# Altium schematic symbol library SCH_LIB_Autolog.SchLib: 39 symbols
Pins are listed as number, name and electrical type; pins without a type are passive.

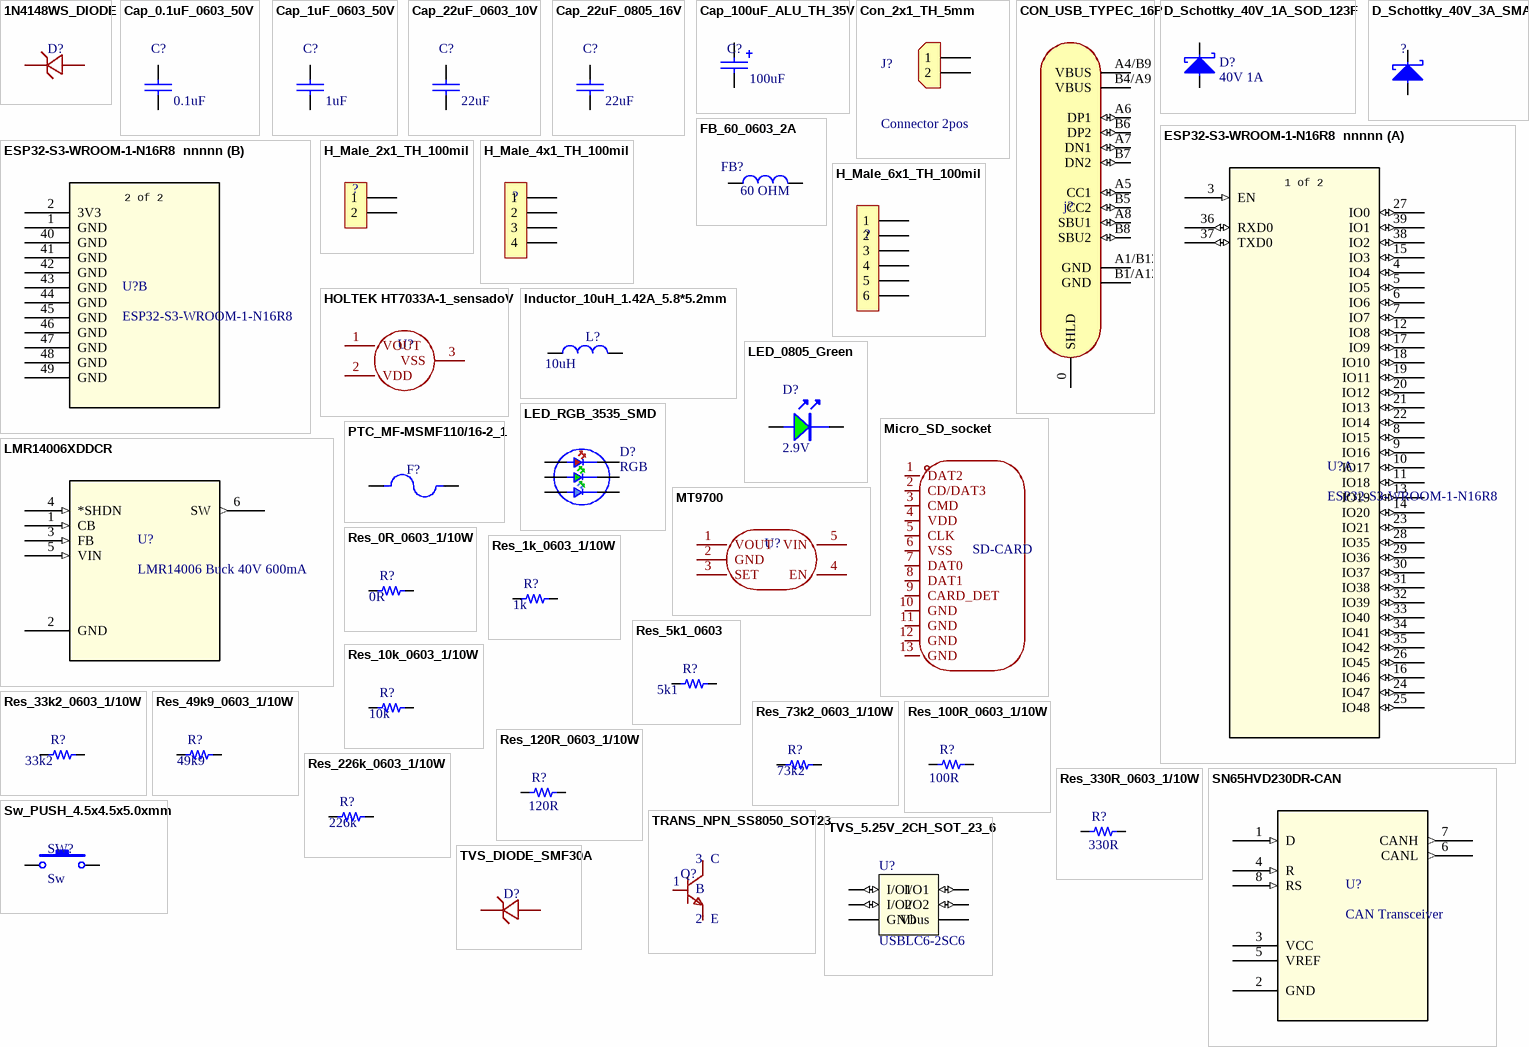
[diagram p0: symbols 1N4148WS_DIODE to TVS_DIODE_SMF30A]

## 1N4148WS_DIODE
designator D?, comment 1N4148WS  (value not drawn)
DIODE GP 100V 150mA SOD-323; Manufacturer: JSCJ
footprint SOD-323_1N4148
pins: 1, 2

## Cap_0.1uF_0603_50V
designator C?, comment value 0.1uF  (hidden comment: 0.1uF 50V)
50V 100nF Y5V -20%~+80% 0603 Multilayer Ceramic Capacitors MLCC - SMD/SMT ROHS; Manufacturer: Walsin Tech Corp; Manufacturer Part Number: 0603F104Z500CT
footprint 0603_cap
pins: 1, 2

## Cap_1uF_0603_50V
designator C?, comment value 1uF  (hidden comment: 1uF 50V)
50V 1uF X5R ±10% 0603 Multilayer Ceramic Capacitors MLCC - SMD/SMT ROHS; Manufacturer: Samsung Electro-Mechanics; Manufacturer Part Number: CL10A105KB8NNNC
footprint 0603_cap
pins: 1, 2

## Cap_22uF_0603_10V
designator C?, comment value 22uF  (hidden comment: 22uF 10V)
10V 22uF X5R ±20% 0603 Multilayer Ceramic Capacitors MLCC - SMD/SMT ROHS; Manufacturer: HRE; Manufacturer Part Number: CGA0603X5R226M100JT
footprint 0603_cap
pins: 1, 2

## Cap_22uF_0805_16V
designator C?, comment value 22uF  (hidden comment: 22uF 16V)
16V 22uF X5R ±20% 0805 Multilayer Ceramic Capacitors MLCC - SMD/SMT ROHS; Manufacturer: Chinocera; Manufacturer Part Number: HGC0805R5226M160NSLJ
footprint 0805_cap
pins: 1, 2

## Cap_100uF_ALU_TH_35V
designator C?, comment value 100uF  (hidden comment: 100uF 35V)
100uF 35V ±20% Plugin,D6.3xL12mm Aluminum Electrolytic Capacitors - Leaded ROHS; Manufacturer: HRK; Manufacturer Part Number: 35V100uF CD110
footprint CAP_TH_2.5MM_6.3*12MM
pins: 1, 2

## Con_2x1_TH_5mm
designator J?, comment Connector 2pos
2POS 5MM; Manufacturer: JILN; Manufacturer Part Number: JL126-50002G01
footprint CON_2x1_TH_5MM (Footprint not found)
pins: 1, 2

## CON_USB_TYPEC_16P
designator j?, comment USB C  (value not drawn)
3A USB 3.1 1 Surface Mount 16P Female -40℃~+85℃ Type-C SMD USB Connectors ROHS; Manufacturer: SHOU HAN; Manufacturer Part Number: TYPE-C-3.1-16PIN
footprint CON_USB_C_16P_RA
pins: 0 SHLD, A1/B12 GND (power), A4/B9 VBUS (power), A5 CC1 (io), A6 DP1 (io), A7 DN1 (io), A8 SBU1 (io), B1/A12 GND (power), B4/A9 VBUS (power), B5 CC2 (io), B6 DP2 (io), B7 DN2 (io), B8 SBU2 (io)

## D_Schottky_40V_1A_SOD_123F
designator D?, comment 40V 1A
DIODE SCHOTTKY 40V 1A SOD123F; Manufacturer: Shanghai Prisemi Elec; Manufacturer Part Number: PSBD1DF40V1H
footprint SOD_123 (/ 20191030 / V-A.Patino)
pins: 1, 2

## D_Schottky_40V_3A_SMA
designator ?, comment 30V 3A  (value not drawn)
40V Independent 3A 550mV@3A SMA Schottky Diodes ROHS; Manufacturer: TDSEMIC; Manufacturer Part Number: SS34-TD
footprint SMA
pins: 1, 2

## ESP32-S3-WROOM-1-N16R8  nnnnn
designator U?, comment ESP32-S3-WROOM-1-N16R8
ESP32-S3 Wi-Fi & Bluetooth 5 MCU module, 16MB Flash, 8MB PSRAM.; Manufacturer: Espressif Systems; Suplier  Part Number: 5407-ESP32-S3-WROOM-1-N16R8TR-ND
footprint ESP32S3WROOM1N8R2
part A pins: 3 EN (in), 4 IO4 (io), 5 IO5 (io), 6 IO6 (io), 7 IO7 (io), 8 IO15 (io), 9 IO16 (io), 10 IO17 (io), 11 IO18 (io), 12 IO8 (io), 13 IO19 (io), 14 IO20 (io), 15 IO3 (io), 16 IO46 (io), 17 IO9 (io), 18 IO10 (io), 19 IO11 (io), 20 IO12 (io), 21 IO13 (io), 22 IO14 (io), 23 IO21 (io), 24 IO47 (io), 25 IO48 (io), 26 IO45 (io), 27 IO0 (io), 28 IO35 (io), 29 IO36 (io), 30 IO37 (io), 31 IO38 (io), 32 IO39 (io), 33 IO40 (io), 34 IO41 (io), 35 IO42 (io), 36 RXD0 (io), 37 TXD0 (io), 38 IO2 (io), 39 IO1 (io)
part B pins: 1 GND (power), 2 3V3 (power), 40 GND (power), 41 GND (power), 42 GND (power), 43 GND (power), 44 GND (power), 45 GND (power), 46 GND (power), 47 GND (power), 48 GND (power), 49 GND (power)

## FB_60_0603_2A
designator FB?, comment value 60 OHM  (hidden comment: 60OHM 2A)
2A 1 100mΩ 60Ω@100MHz ±25% 0603 Ferrite Beads ROHS; Manufacturer: TAI-TECH; Manufacturer Part Number: HCB1608KF-600T20
footprint 0603_fb
pins: 1, 2

## H_Male_2x1_TH_100mil
designator ?, comment 2x1  (value not drawn)  (no BOM)
H_Male_2x1_TH_100mil
footprint H_2x1_TH_100mil
pins: 1, 2

## H_Male_4x1_TH_100mil
designator ?, comment 4x1  (value not drawn)  (no BOM)
H_Male_4x1_TH_100mil
footprint H_4x1_TH_2.54mm
pins: 1, 2, 3, 4

## H_Male_6x1_TH_100mil
designator ?, comment 6x1  (value not drawn)  (no BOM)
H_Male_6x1_TH_100mil
footprint H_6x1_TH_100mil
pins: 1, 2, 3, 4, 5, 6

## HOLTEK HT7033A-1_sensadoV
designator U?
Detector de tensión con umbral de 3.3V; Manufacturer: HOLTEK; Manufacturer product number: HT7033A-1; Suplier  Part Number: C73715
footprint SOT-89-3_L4.5-W2.5-P1.50-LS4.2-BR
pins: 1 VOUT, 2 VDD, 3 VSS

## Inductor_10uH_1.42A_5.8*5.2mm
designator L?, comment value 10uH  (hidden comment: 10uH 1.42A)
1.42A 10uH ±10% 87.9mΩ SMD,5.8x5.2mm Inductors (SMD) ROHS; Manufacturer: SHOU HAN; Manufacturer Part Number: CY54-10UH
footprint Ind_5.8*5.2_NS
pins: 1, 2

## LED_0805_Green
designator D?, comment 2.9V
LED GREEN CLEAR 0805 SMD; Manufacturer: XINGLIGHT; Manufacturer Part Number: XL-2012UGC
footprint 0805_LED
pins: 1 A, 2

## LED_RGB_3535_SMD
designator D?, comment RGB
-30℃~+85℃ RGB 110° 3535(mm) Light Emitting Diodes (LED) ROHS; Manufacturer: Foshan NationStar Optoelectronics; Manufacturer Part Number: RS-3535MWAM
footprint RGB_NS_3.5X3.7
pins: 1, 2, 3, 4, 5, 6

## LMR14006XDDCR
designator U?, comment LMR14006 Buck 40V 600mA
IC REG BUCK ADJ 600MA SOT23; Manufacturer: Texas Instruments; Manufacturer product number: LMR14006XDDCR; Suplier  Part Number: 296-44318-2-ND
footprint DDC6_TEX-M
pins: 1 CB (in), 2 GND (power), 3 FB (in), 4 *SHDN (in), 5 VIN (in), 6 SW (out)

## Micro_SD_socket
designator SD-CARD
CONN MICROSD CARD R/A SMD; Manufacturer: ATOM; Manufacturer Part Number: MR01A-01211
footprint MICROSD CARD SMD
pins: 1 DAT2, 2 CD/DAT3, 3 CMD, 4 VDD, 5 CLK, 6 VSS, 7 DAT0, 8 DAT1, 9 CARD_DET, 10 GND, 11 GND, 12 GND, 13 GND

## MT9700
designator U?
Switch de potencia con límite de corriente y control enable para corte en sleep de periféricos y MicroSD; Manufacturer: XI'AN Aerosemi Tech; Manufacturer Part Number: MT9700
footprint SOT-23-5_L3.0-W1.7-P0.95-LS2.8-BR
pins: 1 VOUT, 2 GND, 3 SET, 4 EN, 5 VIN

## PTC_MF-MSMF110/16-2_1
designator F?, comment PTC Resettable Fuse 16V 1.1 A  (value not drawn)
Polymeric PTC Resettable Fuse 16V 1.1 A Ih Surface Mount 1812 (4532 Metric), Concave; Manufacturer: Bourns Inc.; Manufacturer Part Number: MF-MSMF110/16-2
footprint FUSER_MF-MSMF110/16-2
pins: 1, 2

## Res_0R_0603_1/10W
designator R?, comment value 0R  (hidden comment: 0R 1/10W)
RES SMD 0R OHM 5% 1/10W 0603; Manufacturer: FOJAN; Manufacturer Part Number: FRC0603P000 TS
footprint 0603_res (1608 Metric / 20190225 / C-A.Serna.A)
pins: 1, 2

## Res_1k_0603_1/10W
designator R?, comment value 1k  (hidden comment: 1k 1/10W)
RES SMD 1k OHM 5% 1/10W 0603; Manufacturer: FOJAN; Manufacturer Part Number: FRC0603J102 TS
footprint 0603_res (1608 Metric / 20190225 / C-A.Serna.A)
pins: 1, 2

## Res_5k1_0603
designator R?, comment value 5k1  (hidden comment: 5k1 1/10W)
RES 5.1kΩ ±1% 100mW 0603; Manufacturer: YAGEO; Manufacturer Part Number: RC0603FR-0773K2L
footprint 0603_res (1608 Metric / 20190225 / C-A.Serna.A)
pins: 1, 2

## Res_10k_0603_1/10W
designator R?, comment value 10k  (hidden comment: 10k 1/10W)
RES SMD 10k OHM 5% 1/10W 0603; Manufacturer: FOJAN; Manufacturer Part Number: FRC0603J103TS
footprint 0603_res (1608 Metric / 20190225 / C-A.Serna.A)
pins: 1, 2

## Res_33k2_0603_1/10W
designator R?, comment value 33k2  (hidden comment: 33k2 1/10W)
100mW Thick Film Resistor 75V ±100ppm/℃ ±1% 33.2kΩ 0603 Chip Resistor - Surface Mount ROHS; Manufacturer: YAGEO; Manufacturer Part Number: RC0603FR-0733K2L
footprint 0603_res (1608 Metric / 20190225 / C-A.Serna.A)
pins: 1, 2

## Res_49k9_0603_1/10W
designator R?, comment value 49k9  (hidden comment: 49k9 1/10W)
100mW Thick Film Resistor 75V ±100ppm/℃ ±1% 49.9kΩ 0603 Chip Resistor - Surface Mount ROHS; Manufacturer: YAGEO; Manufacturer Part Number: RC0603FR-0749K9L
footprint 0603_res (1608 Metric / 20190225 / C-A.Serna.A)
pins: 1, 2

## Res_73k2_0603_1/10W
designator R?, comment value 73k2  (hidden comment: 73k2 1/10W)
100mW Thick Film Resistor 75V ±100ppm/℃ ±1% 73.2kΩ 0603 Chip Resistor - Surface Mount ROHS; Manufacturer: YAGEO; Manufacturer Part Number: RC0603FR-0773K2L
footprint 0603_res (1608 Metric / 20190225 / C-A.Serna.A)
pins: 1, 2

## Res_100R_0603_1/10W
designator R?, comment value 100R  (hidden comment: 100R 1/10W)
RES SMD 100R OHM 5% 1/10W 0603; Manufacturer: FOJAN; Manufacturer Part Number: FRC0603J101 TS
footprint 0603_res (1608 Metric / 20190225 / C-A.Serna.A)
pins: 1, 2

## Res_120R_0603_1/10W
designator R?, comment value 120R  (hidden comment: 120R 1/10W)
100mW Thick Film Resistor 75V ±100ppm/℃ ±1% 120Ω 0603 Chip Resistor - Surface Mount ROHS; Manufacturer: FOJAN; Manufacturer Part Number: FRC0603F1200TS
footprint 0603_res (1608 Metric / 20190225 / C-A.Serna.A)
pins: 1, 2

## Res_226k_0603_1/10W
designator R?, comment value 226k  (hidden comment: 226k 1/10W)
100mW Thick Film Resistors 75V ±100ppm/℃ ±1% 226kΩ 0603 Chip Resistor - Surface Mount ROHS; Manufacturer: YAGEO; Manufacturer Part Number: RC0603FR-07226KL
footprint 0603_res (1608 Metric / 20190225 / C-A.Serna.A)
pins: 1, 2

## Res_330R_0603_1/10W
designator R?, comment value 330R  (hidden comment: 330R 1/10W)
RES SMD 330R OHM 5% 1/10W 0603; Manufacturer: FOJAN; Manufacturer Part Number: FRC0603J331 TS
footprint 0603_res (1608 Metric / 20190225 / C-A.Serna.A)
pins: 1, 2

## SN65HVD230DR-CAN
designator U?, comment CAN Transceiver
Transceiver Half CANbus 8-SOIC; Manufacturer: Texas Instruments; Manufacturer product number: SN65HVD230DR; Suplier  Part Number: 296-11654-2-ND
footprint D8-M
pins: 1 D (in), 2 GND (power), 3 VCC (power), 4 R (in), 5 VREF (power), 6 CANL (out), 7 CANH (out), 8 RS (in)

## Sw_PUSH_4.5x4.5x5.0xmm
designator SW?, comment Sw
SWITCH TACTILE SPST-NO 0.05A 12V; Manufacturer: BZCN; Manufacturer Part Number: TSC015A05026A
footprint Sw_PUSH_4.5x4.5x5mm
pins: 1, 2

## TRANS_NPN_SS8050_SOT23
designator Q?, comment SS8050  (value not drawn)
SS8050 Transistor BJT NPN 40V 1.5A; Manufacturer: JSCJ; Manufacturer Part Number: SS8050(RANGE:200-350)
footprint SOT-23-3_TRANS NPN
pins: 1 B, 2 E, 3 C

## TVS_5.25V_2CH_SOT_23_6
designator U?, comment USBLC6-2SC6
TVS DIODE 5.25V 17V SOT23-6; Manufacturer: STMicroelectronics
footprint SOT_23_6 (/ 20190225 / V-A.Patino)
pins: 1 I/O1 (io), 2 GND (power), 3 I/O2 (io), 4 I/O2 (io), 5 Vbus (power), 6 I/O1 (io)

## TVS_DIODE_SMF30A
designator D?
TVS DIODE 30VWM 48.4VC SOD123F; Manufacturer: Diotec Semiconductor; Manufacturer Part Number: SMF30A
footprint TVS_DIODE_SMF30A
pins: 1, 2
